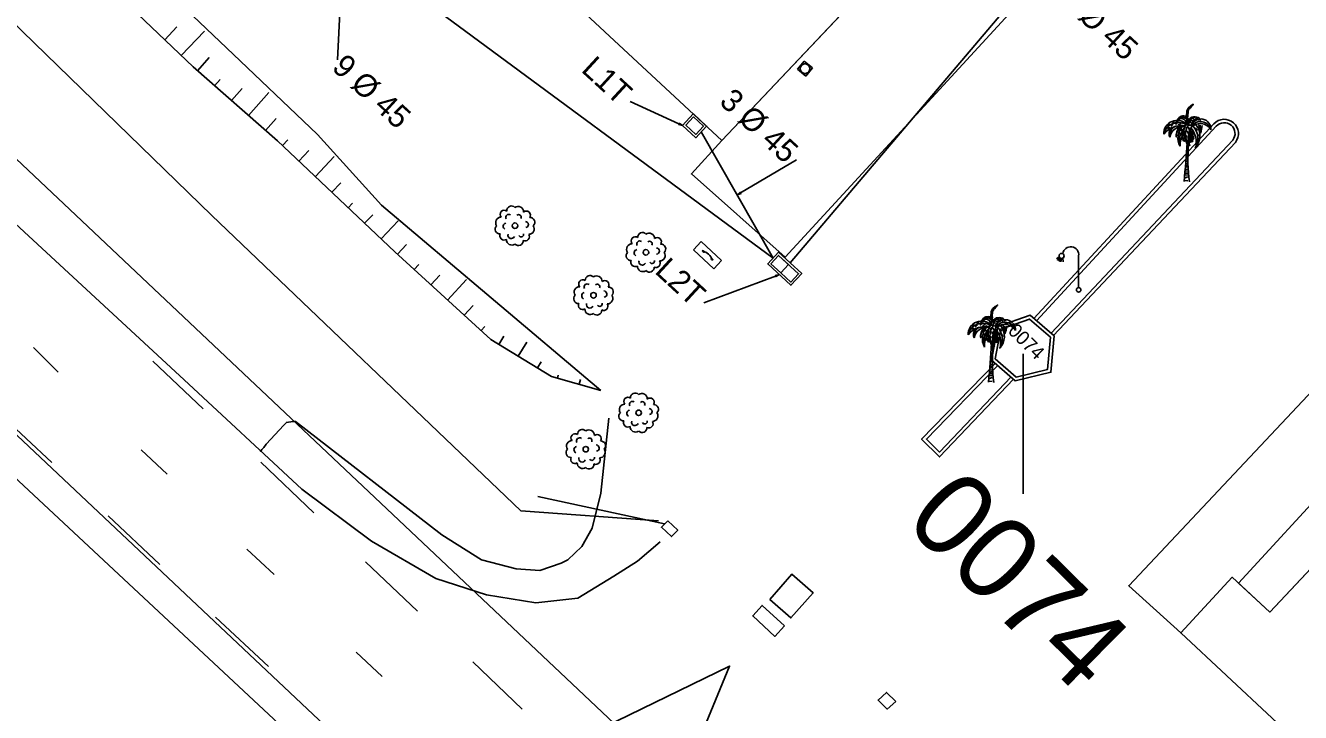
# Model space of a CAD drawing. Extents: x 343997 to 344255, y 298512 to 298767.
# Drawn here: x 344029 to 344085.4, y 298621.1 to 298651.5 of the extents above; entities that cross this region are included whole.
import ezdxf

# ---------------------------------------------------------------- set-up
doc = ezdxf.new("R2010")
doc.units = 0
for name, color, linetype in [('Default', 7, 'Continuous'), ('DH_CADRE -CARTOUCHE', 7, 'Continuous'), ('DH_CADRE-CARTOUCHE', 7, 'Continuous'), ('DH_NORD', 7, 'Continuous'), ('DH_TEXTE', 7, 'Continuous'), ('DIR-Projet VRD1', 7, 'Continuous'), ('GO_DALLE', 7, 'Continuous'), ('GO_MUR', 7, 'Continuous'), ('IMM_VOIRIE VOIE FERREE', 7, 'Continuous'), ('O-Projet New VRD', 7, 'Continuous'), ('PC_REBAR', 7, 'Continuous'), ('PS_BOLT', 7, 'Continuous'), ('PS_HATCH', 7, 'Continuous'), ('PS_KOTE', 7, 'Continuous'), ('PS_MID', 7, 'Continuous'), ('PS_OBJECT', 7, 'Continuous'), ('PS_PLATE', 7, 'Continuous'), ('PS_WELD', 7, 'Continuous'), ('RES_EAU PLUVIALE', 7, 'Continuous'), ('RES_ELECTRICITE', 7, 'Continuous'), ('RES_TELEPHONE SOUTERRAIN', 7, 'Continuous')]:
    doc.layers.add(name, color=color, linetype=linetype)

# ---------------------------------------------------------------- blocks, each defined once
blk = doc.blocks.new('PTT3')
at = {"layer": 'Default'}
for p, q in [((0, 0.1), (0.1, 0.1)), ((0, 0), (0, 0.1)), ((0.1, 0.1), (0.1, 0)), ((0.1, 0), (0, 0))]:
    blk.add_line(p, q, dxfattribs=at)
for centre, radius, start, end in [((0.05, 0.0697), 0.00417, 0, 180), ((0.05, 0.0697), 0.00417, 180, 0), ((0.0395, 0.0494), 0.0229, 297.2754, 62.7246), ((0.05, 0.029), 0.00417, 0, 180), ((0.05, 0.029), 0.00417, 180, 0)]:
    blk.add_arc(centre, radius, start, end, dxfattribs=at)
blk = doc.blocks.new('REG_INC')
at = {"layer": 'Default'}
for p, q in [((0, 0.1), (0.1, 0.1)), ((0, 0), (0, 0.1)), ((0.1, 0), (0, 0)), ((0.1, 0.1), (0.1, 0))]:
    blk.add_line(p, q, dxfattribs=at)
for start, end in [(135.0055, 180.0055), (180.0066, 225.0066), (90.0058, 135.0058), (225.0069, 270.0069), (45.0069, 90.0069), (270.0058, 315.0058), (0.0066, 45.0066), (315.0055, 0.0055)]:
    blk.add_arc((0.05, 0.05), 0.044, start, end, dxfattribs=at)
blk = doc.blocks.new('EDF1')
at = {"layer": 'Default'}
for points in [[(-0.0855, 0.1462), (-0.0985, 0.1373)], [(-0.083, 0.1422), (-0.0931, 0.1303)], [(-0.0793, 0.1397), (-0.086, 0.1257)], [(-0.0753, 0.1388), (-0.0781, 0.1235)], [(-0.0701, 0.14), (-0.0684, 0.1241)], [(0, 0.01), (0, 0.15)]]:
    blk.add_lwpolyline(points, dxfattribs=at)
for centre, radius in [((-0.075, 0.15), 0.0112), ((0, 0), 0.01)]:
    blk.add_circle(centre, radius, dxfattribs=at)
blk.add_arc((-0.035, 0.155), 0.0354, 351.8699, 171.8699, dxfattribs=at)
blk = doc.blocks.new('COCO')
at = {"layer": 'Default'}
for p, q in [((0.0058, 0.114), (-0.003, 0.1162)), ((-0.0026, 0.1226), (0.0061, 0.1212)), ((0.0047, 0.0655), (-0.0058, 0.0642)), ((-0.0046, 0.0891), (0.0052, 0.0927)), ((0.0054, 0.0998), (-0.0041, 0.0985)), ((-0.0037, 0.106), (0.0056, 0.1071)), ((0.0046, 0.0033), (-0.0076, 0.0051)), ((-0.0073, 0.017), (0.0045, 0.0209)), ((0.0045, 0.0292), (-0.007, 0.0288)), ((-0.0068, 0.0371), (0.0045, 0.0374)), ((0.0045, 0.047), (-0.0065, 0.0453)), ((-0.0062, 0.0537), (0.0046, 0.0552))]:
    blk.add_line(p, q, dxfattribs=at)
for points in [[(0.0029, 0.2551), (-0.0016, 0.2896), (0.0002, 0.3125), (0.0059, 0.3241), (0.0173, 0.3348), (0.0189, 0.3356), (0.0282, 0.3415), (0.0266, 0.3373), (0.02, 0.3318), (0.0143, 0.3247), (0.0093, 0.32), (0.0081, 0.3165), (0.0057, 0.3133), (0.0057, 0.3099), (0.006, 0.3037), (0.0039, 0.2989), (0.0039, 0.2944), (0.0049, 0.2877), (0.0037, 0.2841), (0.0013, 0.2736)], [(-0.0746, 0.2559), (-0.0864, 0.2483)], [(-0.077, 0.2413), (-0.0836, 0.2333)], [(-0.0607, 0.2534), (-0.0704, 0.2443)], [(-0.0636, 0.2639), (-0.0541, 0.2608)], [(-0.0421, 0.258), (-0.0503, 0.2523)], [(-0.0487, 0.268), (-0.0386, 0.265)], [(-0.0183, 0.2493), (-0.0348, 0.2417), (-0.0401, 0.2307), (-0.0448, 0.2203), (-0.0471, 0.2086), (-0.0474, 0.2023), (-0.0466, 0.1973), (-0.0455, 0.2054), (-0.0451, 0.2146), (-0.0387, 0.2292), (-0.0351, 0.2354), (-0.0284, 0.2404), (-0.0233, 0.2445), (-0.0012, 0.2495)], [(-0.0256, 0.2553), (-0.0385, 0.2508)], [(-0.0203, 0.2314), (-0.0274, 0.2258)], [(0.0015, 0.2414), (-0.0056, 0.2352)], [(0.0013, 0.2736), (0.0036, 0.2813), (0.0046, 0.2746)], [(0.0081, 0.2404), (0.0106, 0.2299)], [(0.0133, 0.2608), (0.0185, 0.2634)], [(0.0196, 0.2687), (0.0323, 0.2715)], [(0.0283, 0.2765), (0.0331, 0.2786)], [(0.0385, 0.237), (0.0469, 0.2254)], [(-0.0321, 0.1997), (-0.0364, 0.19)], [(-0.0276, 0.2151), (-0.0329, 0.2086)], [(-0.023, 0.2152), (-0.0237, 0.2043)], [(-0.0161, 0.2218), (-0.0158, 0.2122)], [(-0.0059, 0.2024), (-0.0083, 0.1998)], [(-0.004, 0.2247), (-0.0081, 0.2179)], [(-0.0025, 0.2032), (0.0002, 0.1954)], [(0.0022, 0.224), (0.0043, 0.213)], [(0.0473, 0.2115), (0.0509, 0.2012)], [(-0.0055, 0.0716), (0.0048, 0.0717), (0.0049, 0.0787), (-0.0051, 0.0795)]]:
    blk.add_lwpolyline(points, dxfattribs=at)
for centre, radius in [((-0.0187, 0.1897), 0.00384), ((-0.0144, 0.1978), 0.00616), ((-0.0124, 0.1896), 0.00376), ((-0.011, 0.184), 0.00471), ((0.0134, 0.1862), 0.00549), ((0.0208, 0.1822), 0.00626), ((0.0254, 0.1938), 0.00628)]:
    blk.add_circle(centre, radius, dxfattribs=at)
for centre, radius, start, end in [((-0.0123, 0.259), 0.0323, 122.3475, 158.7636), ((-0.0199, 0.2618), 0.0238, 4.5218, 154.101), ((-0.016, 0.2647), 0.0255, 21.0861, 122.3475), ((0.0376, 0.2508), 0.0372, 113.7681, 175.3309), ((0.0376, 0.2508), 0.0372, 113.7681, 175.3309), ((0.0418, 0.2527), 0.0326, 97.1248, 183.9512), ((0.1025, 0.2053), 0.0958, 126.6858, 153.1664), ((0.0344, 0.2407), 0.0451, 69.0817, 104.862), ((0.0493, 0.2767), 0.00679, 35.3205, 126.6858), ((-0.0427, 0.2113), 0.0595, 43.6121, 181.4625), ((-0.0291, 0.1543), 0.0918, 76.7389, 142.8025), ((-0.038, 0.1964), 0.0648, 57.9192, 166.6201), ((-0.03, 0.212), 0.0482, 151.1331, 199.5942), ((-0.0196, 0.1874), 0.0565, 78.514, 171.3504), ((-0.032, 0.2055), 0.0433, 119.0834, 188.7621), ((-0.0252, 0.2556), 0.0231, 4.2441, 134.2103), ((0.0362, 0.1922), 0.0754, 136.7113, 208.8221), ((0.0551, 0.179), 0.0879, 137.733, 194.3716), ((0.062, 0.2159), 0.0753, 153.0868, 230.1124), ((0.0659, 0.2068), 0.0718, 142.3554, 222.2794), ((-0.0007, 0.2465), 0.00563, 81.7475, 144.3035), ((-0.0189, 0.121), 0.1324, 71.3715, 81.7475), ((0.0294, 0.2595), 0.0256, 198.6765, 199.7627), ((0.0963, 0.1939), 0.09, 143.9866, 203.4288), ((0.0311, 0.2152), 0.0219, 141.856, 191.5175), ((0.0398, 0.2098), 0.0301, 136.4569, 162.0685), ((0.0357, 0.2084), 0.0244, 133.1184, 172.7534), ((-0.0404, 0.2045), 0.0619, 329.4666, 26.6793), ((0.059, 0.2015), 0.0548, 29.5654, 139.3517), ((-0.0543, 0.1744), 0.096, 344.8781, 41.1461), ((-0.0341, 0.19), 0.0828, 46.9767, 50.1231), ((0.0618, 0.2316), 0.0451, 356.1627, 159.0009), ((0.0609, 0.2187), 0.0468, 12.1077, 148.3146), ((-0.0157, 0.2027), 0.074, 51.2475, 54.5217), ((-0.0341, 0.19), 0.0828, 334.0687, 41.194), ((-0.1005, 0.1577), 0.1786, 37.5668, 40.5156), ((-0.0157, 0.2027), 0.074, 315.1472, 39.0239), ((-0.0254, 0.228), 0.0869, 28.4725, 37.0965), ((-0.1704, 0.1849), 0.2327, 7.5978, 16.3666), ((-0.0054, 0.2379), 0.0738, 25.8194, 35.3205), ((-0.0254, 0.228), 0.0869, 350.8883, 14.7063), ((-0.0482, 0.2552), 0.1161, 339.3597, 356.5925), ((0.0649, 0.1599), 0.0949, 145.5146, 182.4528), ((-8.5428, 0.7294), 8.5622, 355.11326, 356.26352), ((-0.0279, 0.1637), 0.0281, 2.1499, 36.6325), ((0.0199, 0.166), 0.0176, 166.9443, 185.5966), ((0.0544, 0.1816), 0.0474, 137.1953, 172.8987), ((0.0308, 0.2014), 0.0226, 121.4297, 182.29), ((2.7302, 0.0106), 2.7266, 175.4791, 176.5597), ((0.0372, 0.1847), 0.0277, 133.5956, 173.487), ((0.0808, 0.1542), 0.0777, 142.2358, 156.28), ((0.0242, 0.1964), 0.0147, 110.9727, 165.9756), ((0.0404, 0.1878), 0.0354, 125.0585, 146.3893), ((-0.0759, 0.1958), 0.0922, 344.8505, 15.8988), ((-0.0289, 0.211), 0.0564, 317.8279, 12.3386), ((-0.0265, 0.1505), 0.0316, 339.9997, 25.7228)]:
    blk.add_arc(centre, radius, start, end, dxfattribs=at)
blk.add_ellipse((2.7425, 0.0272), major_axis=(-2.7371, 0.0966), ratio=0.529859, start_param=6.255729, end_param=6.369141, dxfattribs=at)
blk = doc.blocks.new('ARB1')
at = {"layer": 'Default'}
blk.add_circle((0, 0), 0.0122, dxfattribs=at)
for centre, radius, start, end in [((-0.0471, 0.0503), 0.0183, 53.9554, 222.2066), ((-0.0153, 0.0664), 0.0211, 43.6925, 183.5969), ((0.0139, 0.0613), 0.0241, 358.4583, 125.1928), ((0.0501, 0.0468), 0.0183, 325.1444, 131.0175), ((-0.0613, 0.0139), 0.0241, 88.4583, 215.1928), ((-0.0373, -0.0024), 0.0149, 103.7092, 242.3465), ((-0.0276, 0.037), 0.0134, 52.4396, 209.5496), ((0.0164, 0.038), 0.0112, 330.5895, 133.7127), ((0.0458, 0.0052), 0.0137, 276.6214, 88.967), ((0.0613, -0.0139), 0.0241, 268.4583, 35.1928), ((0.0664, 0.0153), 0.0211, 313.6925, 93.5969), ((-0.0664, -0.0153), 0.0211, 133.6925, 273.5969), ((-0.0478, -0.0443), 0.019, 155.2243, 300.9377), ((-0.0163, -0.042), 0.0148, 159.5371, 338.1663), ((0.0271, -0.038), 0.0112, 210.5895, 13.7127), ((0.0448, -0.0483), 0.0188, 243.1323, 33.0297), ((-0.0139, -0.0613), 0.0241, 178.4583, 305.1928), ((0.0153, -0.0664), 0.0211, 223.6925, 3.5969)]:
    blk.add_arc(centre, radius, start, end, dxfattribs=at)

msp = doc.modelspace()

# ---------------------------------------------------------------- linework, layer by layer
at = {"layer": 'DH_CADRE -CARTOUCHE'}
msp.add_lwpolyline([(343997.309, 298660.673), (344147.183, 298520.807), (344245.09, 298625.72), (344095.215, 298765.586)], close=True, dxfattribs=at)
at = {"layer": 'DH_CADRE-CARTOUCHE'}
for points in [[(344073.604, 298638.56), (344081.558, 298647.168)], [(344073.714, 298638.458), (344081.668, 298647.066)], [(344082.4, 298646.449), (344074.364, 298637.918)], [(344082.514, 298646.351), (344074.474, 298637.815)], [(344072.7, 298635.876), (344069.435, 298632.442), (344068.636, 298633.223), (344071.889, 298636.578)], [(344072.592, 298635.979), (344069.431, 298632.656), (344068.847, 298633.226), (344071.997, 298636.474)]]:
    msp.add_lwpolyline(points, dxfattribs=at)
for radius, start in [(0.629, 321.7057), (0.479, 322.4343)]:
    msp.add_arc((344082.02, 298646.741), radius, start, 137.263, dxfattribs=at)
at = {"layer": 'DH_TEXTE'}
msp.add_line((344073.122, 298630.801), (344073.122, 298636.992), dxfattribs=at)
at = {"layer": 'DIR-Projet VRD1'}
for p, q in [((344023.933, 298669.374), (344062.068, 298641.235)), ((344083.757, 298665.698), (344062.821, 298641.017))]:
    msp.add_line(p, q, dxfattribs=at)
msp.add_lwpolyline([(344058.893, 298646.814), (344062.068, 298641.235)], dxfattribs=at)
at = {"layer": 'GO_DALLE'}
msp.add_lwpolyline([(344059.801, 298646.434), (344058.46, 298644.956), (344062.597, 298641.269), (344072.85, 298652.396), (344068.937, 298656.096)], close=True, dxfattribs=at)
msp.add_lwpolyline([(344105.192, 298623.148), (344106.258, 298624.234), (344089.907, 298639.614), (344077.802, 298626.745), (344080.101, 298624.659)], dxfattribs=at)
at = {"layer": 'GO_MUR'}
for points in [[(344072.144, 298638.088), (344071.892, 298636.774), (344072.819, 298635.971), (344074.212, 298636.307), (344074.337, 298637.735), (344073.405, 298638.532)], [(344057.412, 298629.618), (344057.853, 298629.2), (344057.574, 298628.913), (344057.133, 298629.331)], [(344062.568, 298624.966), (344062.143, 298624.504), (344061.169, 298625.409), (344061.581, 298625.874)], [(344067.491, 298621.629), (344067.087, 298622.028), (344066.711, 298621.688), (344067.115, 298621.289)]]:
    msp.add_lwpolyline(points, close=True, dxfattribs=at)
at = {"layer": 'IMM_VOIRIE VOIE FERREE'}
for points in [[(344004.845, 298664.976), (344011.548, 298658.641), (344023.625, 298647.296), (344036.026, 298635.848), (344041.222, 298631.015), (344044.302, 298628.712), (344047.148, 298627.07), (344049.39, 298626.335), (344051.578, 298625.986), (344053.429, 298626.194), (344055.021, 298627.169), (344056.068, 298627.836), (344057.07, 298628.691)], [(344074.933, 298589.956), (344073.98, 298590.843), (344059.741, 298604.247), (344043.778, 298619.111), (344027.338, 298634.596), (344011.457, 298649.631), (344000.234, 298660.034)], [(344030.455, 298636.184), (344029.355, 298637.272)], [(344036.866, 298634.569), (344034.643, 298636.673)], [(344027.896, 298634.308), (344030.175, 298632.195)], [(344035.273, 298631.683), (344034.125, 298632.755)], [(344041.753, 298629.966), (344039.42, 298632.212)], [(344032.667, 298629.837), (344034.954, 298627.685)], [(344039.997, 298627.243), (344038.788, 298628.361)], [(344046.35, 298625.623), (344044.048, 298627.806)], [(344037.413, 298625.36), (344039.746, 298623.177)], [(344044.774, 298622.735), (344043.626, 298623.807)], [(344050.97, 298621.286), (344048.785, 298623.384)]]:
    msp.add_lwpolyline(points, dxfattribs=at)
at = {"layer": 'O-Projet New VRD'}
for points in [[(344043.051, 298655.081), (344042.81, 298649.998)], [(344057.903, 298647.173), (344055.754, 298648.154)], [(344058.542, 298647.612), (344059.13, 298647.071), (344058.656, 298646.556), (344058.067, 298647.098), (344058.541, 298647.613)], [(344058.55, 298647.474), (344058.991, 298647.068), (344058.653, 298646.699), (344058.211, 298647.106), (344058.55, 298647.474)], [(344060.635, 298644.116), (344063.102, 298645.579)], [(344062.305, 298641.492), (344063.335, 298640.544), (344062.861, 298640.029), (344061.83, 298640.977), (344062.305, 298641.492)], [(344062.31, 298641.351), (344062.752, 298640.945), (344062.413, 298640.577), (344062.855, 298640.17), (344063.194, 298640.538), (344062.31, 298641.351), (344061.972, 298640.983), (344062.413, 298640.577)], [(344062.177, 298640.44), (344059.005, 298639.247)]]:
    msp.add_lwpolyline(points, dxfattribs=at)
for points in [[(344057.915, 298647.2), (344058.067, 298647.098), (344057.891, 298647.146)], [(344060.65, 298644.09), (344060.48, 298644.024), (344060.62, 298644.142)], [(344062.166, 298640.468), (344062.346, 298640.503), (344062.188, 298640.412)]]:
    msp.add_lwpolyline(points, close=True, dxfattribs=at)
at = {"layer": 'PS_BOLT'}
msp.add_lwpolyline([(344061.922, 298626.14), (344062.891, 298627.253), (344063.846, 298626.422), (344062.861, 298625.322)], close=True, dxfattribs=at)
at = {"layer": 'PS_HATCH'}
msp.add_lwpolyline([(344054.799, 298634.148), (344054.455, 298630.833), (344054.066, 298629.285), (344053.608, 298628.482), (344052.986, 298627.894), (344052.703, 298627.737), (344051.75, 298627.416), (344050.704, 298627.488), (344049.178, 298627.885), (344047.417, 298628.989), (344040.953, 298634.009), (344040.827, 298634.009), (344040.545, 298633.962), (344040.426, 298633.844), (344039.645, 298633.004), (344039.543, 298632.854), (344039.456, 298632.768), (344039.393, 298632.658)], dxfattribs=at)
at = {"layer": 'PS_KOTE'}
msp.add_lwpolyline([(344054.597, 298620.488), (344057.802, 298617.497), (344060.144, 298623.188)], close=True, dxfattribs=at)
at = {"layer": 'PS_MID'}
msp.add_lwpolyline([(344082.656, 298626.853), (344091.108, 298636.05), (344092.582, 298634.665), (344084.042, 298625.579), (344082.656, 298626.853)], dxfattribs=at)
at = {"layer": 'PS_OBJECT'}
for p, q in [((344035.164, 298650.889), (344035.706, 298651.456)), ((344035.887, 298650.198), (344036.916, 298651.274)), ((344036.618, 298649.515), (344037.135, 298650.106)), ((344037.37, 298648.856), (344037.616, 298649.136)), ((344038.122, 298648.196), (344038.589, 298648.729)), ((344038.874, 298647.537), (344039.761, 298648.548)), ((344039.626, 298646.877), (344040.094, 298647.411)), ((344040.371, 298646.21), (344040.602, 298646.455)), ((344041.098, 298645.523), (344041.538, 298645.988)), ((344041.825, 298644.835), (344042.66, 298645.719)), ((344042.551, 298644.148), (344042.948, 298644.567)), ((344043.278, 298643.461), (344043.466, 298643.66)), ((344044.005, 298642.774), (344044.363, 298643.152)), ((344044.732, 298642.086), (344045.487, 298642.885)), ((344045.461, 298641.401), (344045.852, 298641.829)), ((344046.199, 298640.726), (344046.405, 298640.952)), ((344046.937, 298640.052), (344047.329, 298640.48)), ((344047.676, 298639.377), (344048.503, 298640.282)), ((344048.414, 298638.702), (344048.807, 298639.132)), ((344049.152, 298638.027), (344049.32, 298638.211)), ((344049.94, 298637.418), (344050.161, 298637.78)), ((344050.794, 298636.896), (344051.172, 298637.517)), ((344051.647, 298636.375), (344051.809, 298636.64)), ((344052.531, 298635.922), (344052.567, 298636.049)), ((344053.493, 298635.65), (344053.555, 298635.868))]:
    msp.add_line(p, q, dxfattribs=at)
for points in [[(344013.309, 298674.045), (344016.677, 298670.884), (344019.994, 298667.792), (344024.403, 298663.589), (344028.025, 298660.019), (344032.009, 298656.228), (344035.513, 298652.822), (344038.498, 298649.953), (344041.923, 298646.692), (344044.756, 298643.58), (344054.456, 298635.377)], [(344054.456, 298635.377), (344052.269, 298635.996), (344049.579, 298637.638), (344045.345, 298641.507), (344040.154, 298646.415), (344036.423, 298649.686), (344032.732, 298653.214), (344029.519, 298656.25), (344025.888, 298659.813), (344022.228, 298663.281), (344018.635, 298666.633), (344015.082, 298669.913), (344012.021, 298672.665)]]:
    msp.add_lwpolyline(points, dxfattribs=at)
at = {"layer": 'PS_PLATE'}
for points in [[(344050.263, 298661.981), (344060.039, 298672.492), (344055.614, 298676.601), (344042.396, 298662.623), (344059.801, 298646.434), (344073.019, 298660.413), (344068.567, 298664.519), (344058.811, 298654.03)], [(344072.013, 298638.201), (344071.729, 298636.718), (344072.779, 298635.808), (344074.353, 298636.186), (344074.493, 298637.798), (344073.437, 298638.702)]]:
    msp.add_lwpolyline(points, close=True, dxfattribs=at)
msp.add_lwpolyline([(344092.72, 298634.812), (344105.192, 298623.148), (344094.238, 298611.445), (344080.101, 298624.659), (344082.365, 298627.121), (344084.042, 298625.579), (344092.72, 298634.812)], dxfattribs=at)
at = {"layer": 'PS_WELD'}
for points in [[(344037.247, 298643.122), (344026.234, 298653.823), (344009.284, 298669.732)], [(344037.247, 298643.122), (344050.92, 298630.053), (344057.003, 298629.611)], [(344057.273, 298629.474), (344051.665, 298630.685)]]:
    msp.add_lwpolyline(points, dxfattribs=at)
at = {"layer": 'RES_TELEPHONE SOUTERRAIN'}
msp.add_lwpolyline([(344006.37, 298666.609), (344159.504, 298522.019), (344160.824, 298520.82), (344163.6, 298518.226)], dxfattribs=at)

# ---------------------------------------------------------------- block references
at = {"layer": 'DH_NORD', "xscale": 5.04057897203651, "yscale": 12.351923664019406, "rotation": 47.31047999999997}
msp.add_blockref('PTT3', (344059.453, 298640.756), dxfattribs=at)
at = {"layer": 'PC_REBAR', "xscale": 10, "yscale": 10}
for name, p in [('COCO', (344080.367, 298644.617)), ('ARB1', (344050.654, 298642.663)), ('ARB1', (344056.446, 298641.486)), ('ARB1', (344054.126, 298639.588)), ('COCO', (344071.717, 298635.741)), ('ARB1', (344056.124, 298634.392)), ('ARB1', (344053.785, 298632.78))]:
    msp.add_blockref(name, p, dxfattribs=at)
at = {"layer": 'RES_EAU PLUVIALE', "xscale": 4.81518699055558, "yscale": 4.74988611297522, "rotation": -39.587399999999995}
msp.add_blockref('REG_INC', (344063.145, 298649.58), dxfattribs=at)
at = {"layer": 'RES_ELECTRICITE', "xscale": 10, "yscale": 10}
msp.add_blockref('EDF1', (344075.581, 298639.829), dxfattribs=at)

# ---------------------------------------------------------------- texts
at = {"layer": 'DH_TEXTE'}
for height, p in [(0.6107, (344072.414, 298637.967)), (3.662, (344067.796, 298629.537))]:
    msp.add_text('0074', height=height, rotation=315.3665, dxfattribs=at).set_placement(p)
at = {"layer": 'O-Projet New VRD'}
for s, p in [('9 Ø 45', (344074.681, 298652.627)), ('9 Ø 45', (344042.508, 298649.602)), ('L1T', (344053.541, 298649.509)), ('3 Ø 45', (344059.645, 298648.087)), ('L2T', (344056.792, 298640.601))]:
    msp.add_text(s, height=1.0003, rotation=317.3672, dxfattribs=at).set_placement(p)

doc.saveas('drawing.dxf')
